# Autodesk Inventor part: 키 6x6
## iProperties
Company: 한국ATC센터
Created: 2013-01
Part Number: 키 6x6
Document SubType Name: Modeling
Designer: KYOUNG IL JANG
Density: 7.25 g/cm^3
Material: 주철
Mass: 4.36193 g
Surface Area: 4.57646 cm^2
Volume: 0.601646 cm^3
Author: KYOUNG IL JANG
